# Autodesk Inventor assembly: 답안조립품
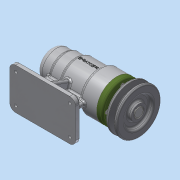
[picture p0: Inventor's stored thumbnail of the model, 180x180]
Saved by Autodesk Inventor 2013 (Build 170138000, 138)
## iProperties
Created: 2016-06
Part Number: 답안조립품
Document SubType Name: Assembly
Designer: Administrator
Author: Administrator
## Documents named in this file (11)
- C:\Users\Administrator\Desktop\460608V1005\답안조립품.iam
- C:\Users\Administrator\Desktop\460608V1005\본체.ipt
- C:\Users\Administrator\Desktop\460608V1005\축.ipt
- C:\Users\Administrator\Desktop\460608V1005\키 5 x 5 x 16.ipt
- C:\Users\Administrator\Desktop\460608V1005\V벨트풀리.ipt
- C:\Users\Administrator\Desktop\460608V1005\멈춤나사 M3x8.ipt
- C:\Users\Administrator\Desktop\460608V1005\베어링 51202.ipt
- C:\Users\Administrator\Desktop\460608V1005\어댑터슬리브.ipt
- C:\Users\Administrator\Desktop\460608V1005\베어링 6004.ipt
- C:\Users\Administrator\Desktop\460608V1005\볼트 M4 x 12.ipt
- C:\Users\Administrator\Desktop\460608V1005\커버.ipt
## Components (6 placed, 2 different names)
1. V벨트풀리:1 — 각도:2
2. ISO 4762 M4 x 12:1 — 각도:2
3. ISO 4762 M4 x 12:2 — 각도:3
4. ISO 4762 M4 x 12:3
5. ISO 4762 M4 x 12:4
6. ISO 4762 M4 x 12:5
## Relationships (2: Angle 2)
- 각도:2 [Angle]: V벨트풀리:1 ↔ ISO 4762 M4 x 12:1
- 각도:3 [Angle]: ISO 4762 M4 x 12:2
